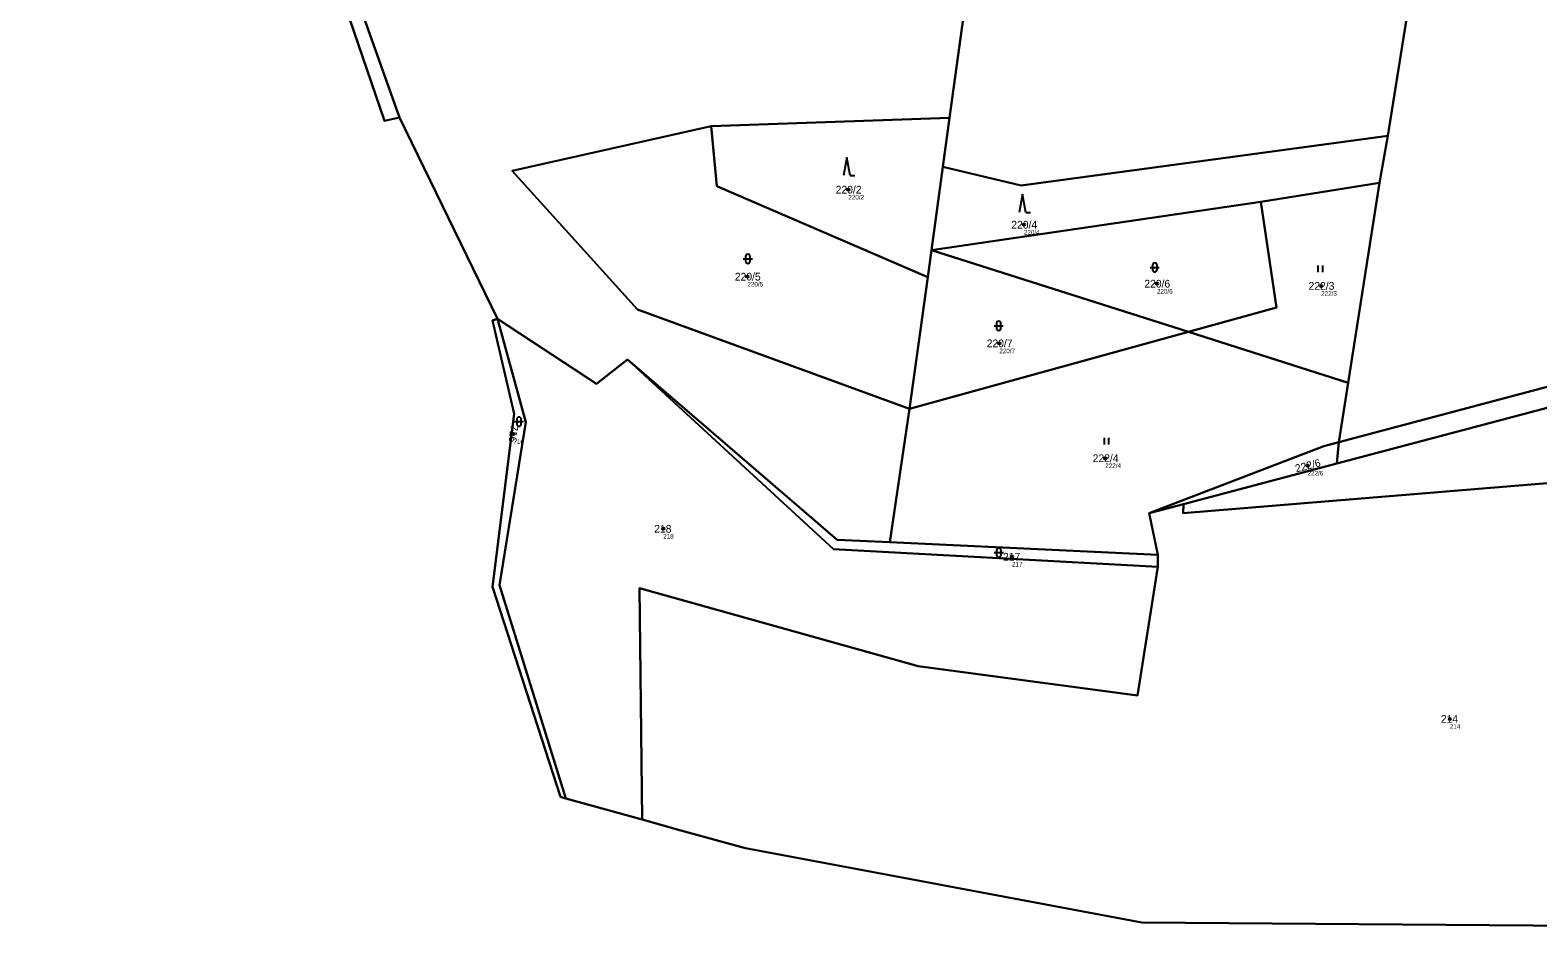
# Model space of a CAD drawing. Extents: x -767985 to -763816, y -1059600 to -1057360.
# Drawn here: x -767964.2 to -767632.7, y -1058818.4 to -1058616.3 of the extents above; entities that cross this region are included whole.
import ezdxf

# ---------------------------------------------------------------- set-up
doc = ezdxf.new("R2010")
doc.units = 0
for name, color, linetype in [('Definiční body', 7, 'Continuous'), ('Hranice parcel', 7, 'Continuous'), ('Parcelní čísla', 7, 'Continuous'), ('Polygon ku', 7, 'Continuous'), ('Polygon parcely', 7, 'Continuous'), ('Značky kultur', 7, 'Continuous')]:
    doc.layers.add(name, color=color, linetype=linetype)

msp = doc.modelspace()

# ---------------------------------------------------------------- linework, layer by layer
at = {"layer": 'Definiční body'}
for centre in [(-767784.35, -1058651.32994), (-767745.74, -1058659.03994), (-767806.53, -1058670.44994), (-767716.48, -1058671.99994), (-767680.37, -1058672.47994), (-767751.15, -1058685.10994), (-767857.98, -1058705.03994), (-767727.84, -1058710.34994), (-767683.37, -1058711.98994), (-767825.05, -1058725.85994), (-767748.35, -1058731.99994), (-767652.08, -1058767.64994)]:
    msp.add_circle(centre, 0.25, dxfattribs=at)
at = {"layer": 'Hranice parcel'}
for p, q in [((-767665.74, -1058639.52), (-767642.35, -1058493.27)), ((-767762.06, -1058635.51), (-767751.99, -1058562.29)), ((-767891.76, -1058611.01), (-767883.04, -1058635.48)), ((-767883.04, -1058635.48), (-767886.34, -1058636.21)), ((-767861.46, -1058679.74), (-767883.04, -1058635.48)), ((-767762.06, -1058635.51), (-767814.53, -1058637.35)), ((-767763.55, -1058646.34), (-767762.06, -1058635.51)), ((-767667.53, -1058649.83), (-767665.74, -1058639.52)), ((-767766.03, -1058664.61), (-767763.55, -1058646.34)), ((-767693.67, -1058654.02), (-767667.53, -1058649.83)), ((-767674.43, -1058693.76), (-767667.53, -1058649.83)), ((-767766.03, -1058664.61), (-767693.67, -1058654.02)), ((-767766.88, -1058670.59), (-767766.03, -1058664.61)), ((-767766.03, -1058664.61), (-767709.53, -1058682.59)), ((-767770.86, -1058699.52), (-767766.88, -1058670.59)), ((-767770.86, -1058699.52), (-767709.53, -1058682.59)), ((-767709.53, -1058682.59), (-767674.43, -1058693.76)), ((-767676.48, -1058706.8), (-767674.43, -1058693.76)), ((-767775.18, -1058728.81), (-767770.86, -1058699.52)), ((-767676.48, -1058706.8), (-767676.91, -1058711.51)), ((-767676.91, -1058711.51), (-767710.67, -1058720.45)), ((-767710.67, -1058720.45), (-767718.17, -1058722.44)), ((-767718.17, -1058722.44), (-767716.28, -1058731.6)), ((-767716.28, -1058731.6), (-767775.18, -1058728.81)), ((-767716.3, -1058734.21), (-767716.28, -1058731.6)), ((-767846.47, -1058785.11), (-767847.66, -1058784.79)), ((-767829.65, -1058789.78), (-767846.47, -1058785.11)), ((-767821.16, -1058792.14), (-767829.65, -1058789.78)), ((-767806.96, -1058796.08), (-767821.16, -1058792.14))]:
    msp.add_line(p, q, dxfattribs=at)
for points in [[(-767886.34, -1058636.21), (-767898.77, -1058599.74), (-767919.26, -1058540.11)], [(-767814.53, -1058637.35), (-767858.27, -1058647.18), (-767830.72, -1058677.63), (-767770.86, -1058699.52)], [(-767814.53, -1058637.35), (-767813.28, -1058650.54), (-767766.88, -1058670.59)], [(-767665.74, -1058639.52), (-767746.35, -1058650.42), (-767763.55, -1058646.34)], [(-767709.53, -1058682.59), (-767690.2, -1058677.25), (-767693.67, -1058654.02)], [(-767498.78, -1058658.75), (-767568.55, -1058671.98), (-767609.45, -1058689.01), (-767676.48, -1058706.8)], [(-767676.91, -1058711.51), (-767611.85, -1058694.28), (-767569.49, -1058676.85), (-767499.53, -1058662.71)], [(-767857.81, -1058700.6), (-767862.56, -1058680.11), (-767861.46, -1058679.74)], [(-767832.9, -1058688.67), (-767839.72, -1058694.01), (-767861.46, -1058679.74)], [(-767861.46, -1058679.74), (-767855.24, -1058702.42), (-767861.07, -1058738.22), (-767846.47, -1058785.11)], [(-767775.18, -1058728.81), (-767786.81, -1058728.26), (-767832.9, -1058688.67)], [(-767832.9, -1058688.67), (-767787.57, -1058730.34), (-767716.3, -1058734.21)], [(-767847.66, -1058784.79), (-767862.56, -1058738.65), (-767857.81, -1058700.6)], [(-767718.17, -1058722.44), (-767679.79, -1058707.68), (-767676.48, -1058706.8)], [(-767513.13, -1058720.35), (-767549.11, -1058714.8), (-767613.71, -1058714.41), (-767710.71, -1058722.42), (-767710.67, -1058720.45)], [(-767829.65, -1058789.78), (-767830.26, -1058738.91), (-767768.99, -1058756.05), (-767720.76, -1058762.48), (-767716.3, -1058734.21)], [(-767572.47, -1058818.39), (-767624.32, -1058813.15), (-767719.79, -1058812.42), (-767806.96, -1058796.08)]]:
    msp.add_lwpolyline(points, dxfattribs=at)
at = {"layer": 'Polygon ku'}
msp.add_lwpolyline([(-767964.25, -1058402.31), (-767956.13, -1058425.91), (-767940.84, -1058470.36), (-767939.03, -1058475), (-767932.06, -1058492.93), (-767934.16, -1058493.56), (-767925.47, -1058522.16), (-767924.19, -1058525.85), (-767919.75, -1058538.7), (-767919.26, -1058540.11), (-767898.77, -1058599.74), (-767886.34, -1058636.21), (-767883.04, -1058635.48), (-767861.46, -1058679.74), (-767862.56, -1058680.11), (-767857.81, -1058700.6), (-767862.56, -1058738.65), (-767847.66, -1058784.79), (-767846.47, -1058785.11), (-767829.65, -1058789.78), (-767821.16, -1058792.14), (-767806.96, -1058796.08), (-767719.79, -1058812.42), (-767624.32, -1058813.15)], dxfattribs=at)
at = {"layer": 'Polygon parcely'}
for points in [[(-767665.74, -1058639.52), (-767642.35, -1058493.27), (-767644, -1058493.28), (-767685.82, -1058532.81), (-767706.32, -1058547.51), (-767746.4, -1058561.11), (-767751.99, -1058562.29), (-767762.06, -1058635.51), (-767763.55, -1058646.34), (-767746.35, -1058650.42)], [(-767665.74, -1058639.52), (-767667.53, -1058649.83), (-767674.43, -1058693.76), (-767676.48, -1058706.8), (-767609.45, -1058689.01), (-767568.55, -1058671.98), (-767498.78, -1058658.75), (-767491.28, -1058619.28), (-767460.92, -1058533.86), (-767460.16, -1058529.59), (-767471.62, -1058531.39), (-767554.21, -1058513.56), (-767592.15, -1058500.66), (-767607.2, -1058493.14), (-767642.35, -1058493.27)], [(-767918.19, -1058538.18), (-767919.75, -1058538.7), (-767919.26, -1058540.11), (-767898.77, -1058599.74), (-767886.34, -1058636.21), (-767883.04, -1058635.48), (-767891.76, -1058611.01), (-767892.63, -1058608.51), (-767914.97, -1058546.84)], [(-767891.76, -1058611.01), (-767883.04, -1058635.48), (-767861.46, -1058679.74), (-767839.72, -1058694.01), (-767832.9, -1058688.67), (-767786.81, -1058728.26), (-767775.18, -1058728.81), (-767770.86, -1058699.52), (-767830.72, -1058677.63), (-767858.27, -1058647.18), (-767814.53, -1058637.35), (-767762.06, -1058635.51), (-767751.99, -1058562.29), (-767825.6, -1058577.87), (-767857.38, -1058591.47)], [(-767770.86, -1058699.52), (-767766.88, -1058670.59), (-767813.28, -1058650.54), (-767814.53, -1058637.35), (-767858.27, -1058647.18), (-767830.72, -1058677.63)], [(-767766.88, -1058670.59), (-767766.03, -1058664.61), (-767763.55, -1058646.34), (-767762.06, -1058635.51), (-767814.53, -1058637.35), (-767813.28, -1058650.54)], [(-767665.74, -1058639.52), (-767746.35, -1058650.42), (-767763.55, -1058646.34), (-767766.03, -1058664.61), (-767693.67, -1058654.02), (-767667.53, -1058649.83)], [(-767674.43, -1058693.76), (-767667.53, -1058649.83), (-767693.67, -1058654.02), (-767690.2, -1058677.25), (-767709.53, -1058682.59)], [(-767690.2, -1058677.25), (-767693.67, -1058654.02), (-767766.03, -1058664.61), (-767709.53, -1058682.59)], [(-767676.91, -1058711.51), (-767611.85, -1058694.28), (-767569.49, -1058676.85), (-767499.53, -1058662.71), (-767498.78, -1058658.75), (-767568.55, -1058671.98), (-767609.45, -1058689.01), (-767676.48, -1058706.8)], [(-767710.67, -1058720.45), (-767710.71, -1058722.42), (-767613.71, -1058714.41), (-767549.11, -1058714.8), (-767513.13, -1058720.35), (-767506.86, -1058701.32), (-767499.53, -1058662.71), (-767569.49, -1058676.85), (-767611.85, -1058694.28), (-767676.91, -1058711.51)], [(-767709.53, -1058682.59), (-767766.03, -1058664.61), (-767766.88, -1058670.59), (-767770.86, -1058699.52)], [(-767847.66, -1058784.79), (-767846.47, -1058785.11), (-767861.07, -1058738.22), (-767855.24, -1058702.42), (-767861.46, -1058679.74), (-767862.56, -1058680.11), (-767857.81, -1058700.6), (-767862.56, -1058738.65)], [(-767846.47, -1058785.11), (-767829.65, -1058789.78), (-767830.26, -1058738.91), (-767768.99, -1058756.05), (-767720.76, -1058762.48), (-767716.3, -1058734.21), (-767787.57, -1058730.34), (-767832.9, -1058688.67), (-767839.72, -1058694.01), (-767861.46, -1058679.74), (-767855.24, -1058702.42), (-767861.07, -1058738.22)], [(-767679.79, -1058707.68), (-767676.48, -1058706.8), (-767674.43, -1058693.76), (-767709.53, -1058682.59), (-767770.86, -1058699.52), (-767775.18, -1058728.81), (-767716.28, -1058731.6), (-767718.17, -1058722.44)], [(-767787.57, -1058730.34), (-767716.3, -1058734.21), (-767716.28, -1058731.6), (-767775.18, -1058728.81), (-767786.81, -1058728.26), (-767832.9, -1058688.67)], [(-767676.91, -1058711.51), (-767676.48, -1058706.8), (-767679.79, -1058707.68), (-767718.17, -1058722.44), (-767710.67, -1058720.45)], [(-767710.67, -1058720.45), (-767718.17, -1058722.44), (-767716.28, -1058731.6), (-767716.3, -1058734.21), (-767720.76, -1058762.48), (-767768.99, -1058756.05), (-767830.26, -1058738.91), (-767829.65, -1058789.78), (-767821.16, -1058792.14), (-767806.96, -1058796.08), (-767719.79, -1058812.42), (-767624.32, -1058813.15), (-767572.47, -1058818.39), (-767569.26, -1058805.41), (-767513.13, -1058720.35), (-767549.11, -1058714.8), (-767613.71, -1058714.41), (-767710.71, -1058722.42)]]:
    msp.add_lwpolyline(points, close=True, dxfattribs=at)
at = {"layer": 'Značky kultur'}
for p, q in [((-767784.66, -1058644.23), (-767785.41, -1058648.23)), ((-767783.91, -1058648.23), (-767784.66, -1058644.23)), ((-767783.91, -1058648.23), (-767782.914, -1058648.23)), ((-767746.06, -1058652.32), (-767746.81, -1058656.32)), ((-767745.31, -1058656.32), (-767746.06, -1058652.32)), ((-767745.31, -1058656.32), (-767744.314, -1058656.32)), ((-767807.431, -1058666.521), (-767805.429, -1058666.521)), ((-767806.931, -1058666.021), (-767806.931, -1058667.022)), ((-767805.929, -1058667.022), (-767805.929, -1058666.021)), ((-767717.961, -1058668.411), (-767715.959, -1058668.411)), ((-767717.461, -1058667.911), (-767717.461, -1058668.912)), ((-767716.459, -1058668.912), (-767716.459, -1058667.911)), ((-767681.041, -1058669.47), (-767681.041, -1058667.97)), ((-767680.04, -1058669.47), (-767680.04, -1058667.97)), ((-767751.791, -1058680.761), (-767751.791, -1058681.762)), ((-767750.789, -1058681.762), (-767750.789, -1058680.761)), ((-767752.291, -1058681.261), (-767750.289, -1058681.261)), ((-767857.761, -1058702.311), (-767855.759, -1058702.311)), ((-767857.261, -1058701.811), (-767857.261, -1058702.812)), ((-767856.259, -1058702.812), (-767856.259, -1058701.811)), ((-767728.041, -1058707.34), (-767728.041, -1058705.84)), ((-767727.04, -1058707.34), (-767727.04, -1058705.84)), ((-767752.241, -1058731.081), (-767750.239, -1058731.081)), ((-767751.741, -1058730.581), (-767751.741, -1058731.582)), ((-767750.739, -1058731.582), (-767750.739, -1058730.581))]:
    msp.add_line(p, q, dxfattribs=at)
for centre, start, end in [((-767806.43, -1058666.0209), 0, 180), ((-767806.43, -1058667.0209), 180, 359.9878861), ((-767716.96, -1058667.9109), 0, 180), ((-767716.96, -1058668.9109), 180, 359.9878861), ((-767751.29, -1058680.7609), 0, 180), ((-767751.29, -1058681.7609), 180, 359.9878861), ((-767856.76, -1058701.8109), 0, 180), ((-767856.76, -1058702.8109), 180, 359.9878861), ((-767751.24, -1058730.5809), 0, 180), ((-767751.24, -1058731.5809), 180, 359.9878861)]:
    msp.add_arc(centre, 0.5, start, end, dxfattribs=at)

# ---------------------------------------------------------------- texts
at = {"layer": 'Definiční body'}
for s, p in [('220/2', (-767784.35, -1058653.486)), ('220/4', (-767745.74, -1058661.196)), ('220/5', (-767806.53, -1058672.606)), ('220/6', (-767716.48, -1058674.156)), ('222/3', (-767680.37, -1058674.636)), ('220/7', (-767751.15, -1058687.266)), ('716', (-767857.98, -1058707.196)), ('222/4', (-767727.84, -1058712.506)), ('222/6', (-767683.37, -1058714.146)), ('218', (-767825.05, -1058728.016)), ('217', (-767748.35, -1058734.156)), ('214', (-767652.08, -1058769.806))]:
    msp.add_text(s, height=0.999996, dxfattribs=at).set_placement(p)
at = {"layer": 'Parcelní čísla'}
for s, p in [('220/2', (-767787.123, -1058652.18)), ('220/4', (-767748.513, -1058659.89)), ('220/5', (-767809.303, -1058671.3)), ('220/6', (-767719.253, -1058672.85)), ('222/3', (-767683.143, -1058673.33)), ('220/7', (-767753.923, -1058685.96)), ('222/4', (-767730.613, -1058711.2)), ('218', (-767827.024, -1058726.71)), ('217', (-767750.324, -1058732.85)), ('214', (-767654.054, -1058768.5))]:
    msp.add_text(s, height=1.699998, dxfattribs=at).set_placement(p)
for s, rotation, p in [('716', 263, (-767858.582, -1058702.976)), ('222/6', 14, (-767685.855, -1058713.485))]:
    msp.add_text(s, height=1.699998, rotation=rotation, dxfattribs=at).set_placement(p)

doc.saveas('drawing.dxf')
